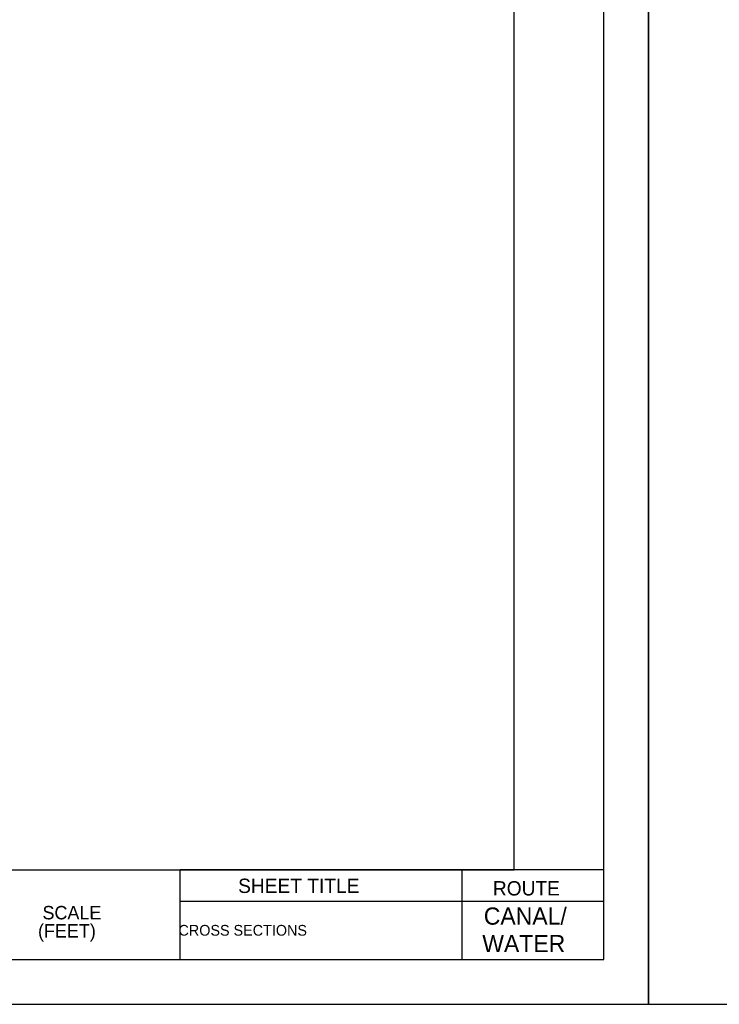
# Model space of a CAD drawing. Extents: x 1797478 to 1808916, y 246529 to 250952.
# Drawn here: x 1803065.7 to 1803143.9, y 250064.4 to 250174.4 of the extents above; entities that cross this region are included whole.
import ezdxf

# ---------------------------------------------------------------- set-up
doc = ezdxf.new("R2010")
doc.units = 0
for name, color, linetype in [('ANNO-SHT', 7, 'Continuous'), ('ANNO-SYMB', 7, 'Continuous'), ('ANNO-TXT', 7, 'Continuous'), ('Level 6', 7, 'Continuous'), ('Level 62', 7, 'Continuous'), ('SHT-BDR', 7, 'Continuous'), ('SHT-BNDRY', 7, 'Continuous')]:
    doc.layers.add(name, color=color, linetype=linetype)

msp = doc.modelspace()

# ---------------------------------------------------------------- linework, layer by layer
at = {"layer": 'ANNO-TXT'}
for p, q in [((1803083.66, 250075.96), (1803115.19, 250075.96)), ((1803115.19, 250075.96), (1803131, 250075.96))]:
    msp.add_line(p, q, dxfattribs=at)
at = {"layer": 'Level 6'}
msp.add_line((1803131, 250079.43), (1803083.66, 250079.43), dxfattribs=at)
at = {"layer": 'Level 62'}
for points in [[(1802796, 250064.42), (1803136, 250064.42), (1803136, 250284.42), (1802796, 250284.42)], [(1803136, 250064.42), (1803476, 250064.42), (1803476, 250284.42), (1803136, 250284.42)]]:
    msp.add_lwpolyline(points, close=True, dxfattribs=at)
at = {"layer": 'SHT-BDR'}
msp.add_lwpolyline([(1802821, 250079.43), (1803121, 250079.43), (1803121, 250269.43), (1802821, 250269.43)], close=True, dxfattribs=at)
at = {"layer": 'SHT-BNDRY'}
for p, q in [((1803083.66, 250069.42), (1803083.66, 250079.43)), ((1803115.19, 250069.42), (1803115.19, 250079.43))]:
    msp.add_line(p, q, dxfattribs=at)
msp.add_lwpolyline([(1802808.5, 250069.42), (1803131, 250069.42), (1803131, 250279.42), (1802808.5, 250279.42)], close=True, dxfattribs=at)

# ---------------------------------------------------------------- texts
at = {"layer": 'ANNO-SHT'}
for s, height, p in [(' CANAL/ ', 1.92, (1803116.89, 250073.32)), ('          CROSS SECTIONS          ', 1.2, (1803079.03, 250072.09)), (' WATER ', 1.92, (1803116.72, 250070.25))]:
    msp.add_text(s, height=height, rotation=360, dxfattribs=at).set_placement(p)
at = {"layer": 'ANNO-SYMB'}
for s, p in [('SCALE', (1803068.29, 250073.91)), ('(FEET)', (1803067.79, 250071.88))]:
    msp.add_text(s, height=1.499, rotation=0.0572, dxfattribs=at).set_placement(p)
at = {"layer": 'ANNO-TXT'}
for s, p in [('SHEET TITLE', (1803090.15, 250076.86)), ('ROUTE', (1803118.62, 250076.58))]:
    msp.add_text(s, height=1.6, dxfattribs=at).set_placement(p)

doc.saveas('drawing.dxf')
